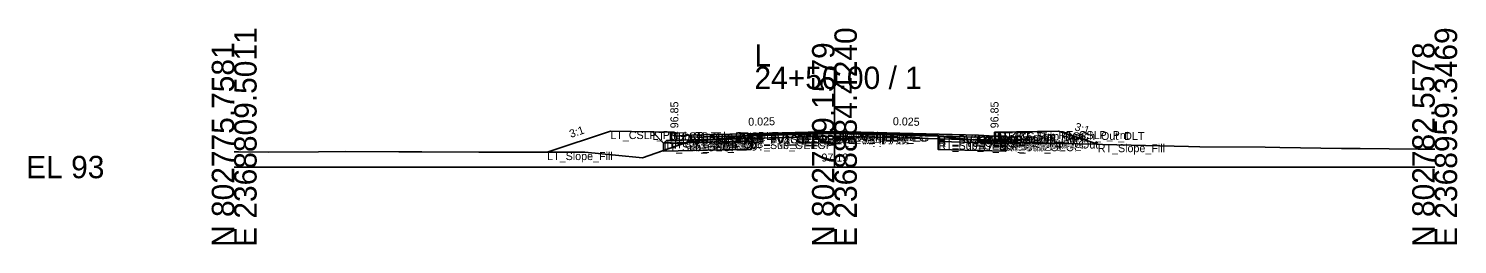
# Model space of a CAD drawing. Extents: x -26 to 8153, y -10 to 9520.
# Drawn here: x 974.3 to 1152.8, y 6990.3 to 7017.3 of the extents above; entities that cross this region are included whole.
import ezdxf

# ---------------------------------------------------------------- set-up
doc = ezdxf.new("R2010")
doc.units = 0
for name, color, linetype in [('Exist CMT Pavement', 7, 'Continuous'), ('Exist Cross Section Cell', 7, 'Continuous'), ('Exist XS Center Line Elevation Label', 7, 'Continuous'), ('Exist XS Ground Line', 7, 'Continuous'), ('Prop CMT Conc Surface', 7, 'Continuous'), ('Prop CMT Concrete Structures', 7, 'Continuous'), ('Prop CMT Pvmt Course 1', 7, 'Continuous'), ('Prop CMT Pvmt Course 1 CG', 7, 'Continuous'), ('Prop CMT Pvmt Course 1 Wedge', 7, 'Continuous'), ('Prop CMT Pvmt Course 2', 7, 'Continuous'), ('Prop CMT Pvmt Course 2 Wedge', 7, 'Continuous'), ('Prop CMT Pvmt Course 3', 7, 'Continuous'), ('Prop CMT Pvmt Course 3 Wedge', 7, 'Continuous'), ('Prop CMT Pvmt Surface', 7, 'Continuous'), ('Prop CMT Pvmt Wedge Surface 1', 7, 'Continuous'), ('Prop CMT Pvmt Wedge Surface 2', 7, 'Continuous'), ('Prop CMT Pvmt Wedge Surface 3', 7, 'Continuous'), ('Prop CMT Shallow Undercut', 7, 'Continuous'), ('Prop CMT Shallow Undercut Boundary', 7, 'Continuous'), ('Prop CMT Slope Grass', 7, 'Continuous'), ('Prop CMT Subgrade Earthwork', 7, 'Continuous'), ('Prop XS Earthwork Shape', 7, 'Continuous'), ('Prop XS Hydro Elevations', 7, 'Continuous'), ('Prop XS SE Text', 7, 'Continuous'), ('Prop XS Side Slope Text', 7, 'Continuous'), ('Prop XS Subgrade Earthwork', 7, 'Continuous'), ('Scratch_Level_2', 7, 'Continuous'), ('Scratch_Level_6', 7, 'Continuous')]:
    doc.layers.add(name, color=color, linetype=linetype)

msp = doc.modelspace()

# ---------------------------------------------------------------- linework, layer by layer
at = {"layer": 'Exist CMT Pavement'}
for p, q in [((1064.64, 7003.97), (1067.28, 7004.03)), ((1067.28, 7004.03), (1074.93, 7004.19)), ((1074.93, 7004.19), (1081.41, 7004.14)), ((1081.41, 7004.14), (1085.45, 7004.12)), ((1085.45, 7004.12), (1087.05, 7003.95)), ((1087.05, 7003.95), (1087.98, 7003.86))]:
    msp.add_line(p, q, dxfattribs=at)
at = {"layer": 'Exist Cross Section Cell'}
for p, q in [((1075, 7000), (1075, 7012.57)), ((1000, 7000), (1075, 7000)), ((1075, 7000), (1150, 7000))]:
    msp.add_line(p, q, dxfattribs=at)
at = {"layer": 'Exist XS Ground Line'}
for p, q in [((1062.93, 7003.77), (1064.64, 7003.97)), ((1064.64, 7003.97), (1067.28, 7004.03)), ((1067.28, 7004.03), (1074.93, 7004.19)), ((1074.93, 7004.19), (1081.41, 7004.14)), ((1081.41, 7004.14), (1085.45, 7004.12)), ((1085.45, 7004.12), (1087.05, 7003.95)), ((1087.05, 7003.95), (1087.98, 7003.86)), ((1087.98, 7003.86), (1089.65, 7003.66)), ((1051.03, 7001.16), (1056.73, 7003.17)), ((1056.73, 7003.17), (1060.65, 7003.54)), ((1060.65, 7003.54), (1062.93, 7003.77)), ((1089.65, 7003.66), (1093.02, 7003.36)), ((1093.02, 7003.36), (1098.57, 7003.08)), ((1098.57, 7003.08), (1100.93, 7002.99)), ((1100.93, 7002.99), (1107.75, 7002.88)), ((1107.75, 7002.88), (1108.48, 7002.82)), ((1108.48, 7002.82), (1119.22, 7002.57)), ((1119.22, 7002.57), (1120.65, 7002.53)), ((1120.65, 7002.53), (1128.8, 7002.48)), ((1128.8, 7002.48), (1130.66, 7002.45)), ((1130.66, 7002.45), (1138.37, 7002.32)), ((1138.37, 7002.32), (1140.67, 7002.32)), ((1140.67, 7002.32), (1147.95, 7002.24)), ((1147.95, 7002.24), (1150, 7002.22)), ((1000, 7001.9), (1000.52, 7001.9)), ((1000.52, 7001.9), (1004.31, 7001.88)), ((1004.31, 7001.88), (1010.53, 7001.9)), ((1010.53, 7001.9), (1013.88, 7001.93)), ((1013.88, 7001.93), (1020.55, 7001.92)), ((1020.55, 7001.92), (1023.46, 7001.92)), ((1023.46, 7001.92), (1030.56, 7001.86)), ((1030.56, 7001.86), (1032.55, 7001.86)), ((1032.55, 7001.86), (1043.8, 7001.87)), ((1043.8, 7001.87), (1047.64, 7001.49)), ((1047.64, 7001.49), (1051.03, 7001.16))]:
    msp.add_line(p, q, dxfattribs=at)
at = {"layer": 'Prop CMT Conc Surface'}
for points in [[(1055, 7003.85), (1055, 7004.35), (1054.5, 7004.35)], [(1057, 7003.98), (1055, 7003.85)], [(1093, 7003.98), (1095, 7003.85)], [(1095, 7003.85), (1095, 7004.35), (1095.5, 7004.35)]]:
    msp.add_lwpolyline(points, dxfattribs=at)
at = {"layer": 'Prop CMT Concrete Structures'}
for points in [[(1057, 7003.98), (1055, 7003.85), (1055, 7004.35), (1054.5, 7004.35)], [(1054.5, 7004.35), (1054.5, 7003.33), (1057, 7003.39)], [(1057, 7003.39), (1057, 7003.98)], [(1093, 7003.98), (1095, 7003.85), (1095, 7004.35), (1095.5, 7004.35)], [(1095.5, 7004.35), (1095.5, 7003.33), (1093, 7003.39)], [(1093, 7003.39), (1093, 7003.98)]]:
    msp.add_lwpolyline(points, dxfattribs=at)
at = {"layer": 'Prop CMT Pvmt Course 1'}
for points in [[(1075, 7004.43), (1057, 7003.98)], [(1057, 7003.98), (1057, 7003.73)], [(1057, 7003.73), (1064.64, 7003.92)], [(1064.64, 7004.04), (1075, 7004.3)], [(1064.64, 7003.92), (1064.64, 7004.04)], [(1075, 7004.18), (1075, 7004.43)], [(1075, 7004.43), (1093, 7003.98)], [(1075, 7004.18), (1075, 7004.43)], [(1075, 7004.3), (1075, 7004.18), (1075, 7004.18)], [(1087.98, 7003.98), (1075, 7004.3)], [(1075, 7004.3), (1075, 7004.18), (1075, 7004.18)], [(1087.98, 7003.85), (1087.98, 7003.98)], [(1093, 7003.73), (1087.98, 7003.85)], [(1093, 7003.98), (1093, 7003.73)]]:
    msp.add_lwpolyline(points, dxfattribs=at)
at = {"layer": 'Prop CMT Pvmt Course 1 CG'}
for points in [[(1057, 7003.39), (1054, 7003.32), (1053.66, 7002.98)], [(1053.66, 7002.98), (1057, 7003.06)], [(1057, 7003.06), (1057, 7003.39)], [(1093, 7003.39), (1096, 7003.32), (1096.34, 7002.98)], [(1093, 7003.06), (1093, 7003.39)], [(1096.34, 7002.98), (1093, 7003.06)]]:
    msp.add_lwpolyline(points, dxfattribs=at)
at = {"layer": 'Prop CMT Pvmt Course 1 Wedge'}
for points in [[(1075, 7004.3), (1064.64, 7004.04)], [(1075, 7004.3), (1087.98, 7003.98)]]:
    msp.add_lwpolyline(points, dxfattribs=at)
at = {"layer": 'Prop CMT Pvmt Course 2'}
for points in [[(1064.64, 7003.92), (1057, 7003.73)], [(1064.64, 7003.59), (1064.64, 7003.92)], [(1087.98, 7003.52), (1087.98, 7003.85)], [(1087.98, 7003.85), (1093, 7003.73)], [(1057, 7003.73), (1057, 7003.4)], [(1057, 7003.4), (1064.64, 7003.59)], [(1093, 7003.4), (1087.98, 7003.52)], [(1093, 7003.73), (1093, 7003.4)]]:
    msp.add_lwpolyline(points, dxfattribs=at)
at = {"layer": 'Prop CMT Pvmt Course 2 Wedge'}
for points in [[(1075, 7004.18), (1064.64, 7003.92)], [(1075, 7004.18), (1087.98, 7003.85)]]:
    msp.add_lwpolyline(points, dxfattribs=at)
at = {"layer": 'Prop CMT Pvmt Course 3'}
for points in [[(1064.64, 7003.59), (1057, 7003.4)], [(1057, 7003.4), (1057, 7003.06)], [(1057, 7003.06), (1064.64, 7003.25)], [(1064.64, 7003.25), (1064.64, 7003.59)], [(1087.98, 7003.52), (1093, 7003.4)], [(1087.98, 7003.19), (1087.98, 7003.52)], [(1093, 7003.06), (1087.98, 7003.19)], [(1093, 7003.4), (1093, 7003.06)]]:
    msp.add_lwpolyline(points, dxfattribs=at)
at = {"layer": 'Prop CMT Pvmt Course 3 Wedge'}
for points in [[(1075, 7003.85), (1064.64, 7003.59)], [(1075, 7003.85), (1087.98, 7003.52)]]:
    msp.add_lwpolyline(points, dxfattribs=at)
at = {"layer": 'Prop CMT Pvmt Surface'}
for points in [[(1075, 7004.43), (1057, 7003.98)], [(1075, 7004.43), (1093, 7003.98)]]:
    msp.add_lwpolyline(points, dxfattribs=at)
at = {"layer": 'Prop CMT Pvmt Wedge Surface 1'}
for points in [[(1057, 7003.73), (1057, 7003.98)], [(1064.64, 7003.92), (1057, 7003.73)], [(1075, 7004.3), (1064.64, 7004.04)], [(1064.64, 7004.04), (1064.64, 7003.92)], [(1075, 7004.3), (1087.98, 7003.98)], [(1087.98, 7003.98), (1087.98, 7003.85)], [(1087.98, 7003.85), (1093, 7003.73)], [(1093, 7003.73), (1093, 7003.98)]]:
    msp.add_lwpolyline(points, dxfattribs=at)
at = {"layer": 'Prop CMT Pvmt Wedge Surface 2'}
for points in [[(1075, 7004.18), (1057, 7003.73)], [(1057, 7003.73), (1057, 7003.98)], [(1075, 7004.18), (1093, 7003.73)], [(1093, 7003.73), (1093, 7003.98)]]:
    msp.add_lwpolyline(points, dxfattribs=at)
at = {"layer": 'Prop CMT Pvmt Wedge Surface 3'}
for points in [[(1057, 7003.4), (1057, 7003.98)], [(1075, 7003.85), (1057, 7003.4)], [(1075, 7003.85), (1093, 7003.4)], [(1093, 7003.4), (1093, 7003.98)]]:
    msp.add_lwpolyline(points, dxfattribs=at)
at = {"layer": 'Prop CMT Shallow Undercut'}
for p, q in [((1096.34, 7002.98), (1087.98, 7003.19)), ((1087.98, 7003.19), (1087.98, 7002.19)), ((1087.98, 7002.19), (1096.34, 7001.98)), ((1096.34, 7001.98), (1096.34, 7002.98))]:
    msp.add_line(p, q, dxfattribs=at)
msp.add_lwpolyline([(1064.64, 7003.25), (1064.64, 7002.25), (1053.66, 7001.98), (1053.66, 7002.09), (1056.4, 7003.05)], close=True, dxfattribs=at)
at = {"layer": 'Prop CMT Shallow Undercut Boundary'}
for p, q in [((1053.66, 7002.98), (1064.64, 7003.25)), ((1053.66, 7002.98), (1053.66, 7001.98)), ((1053.66, 7001.98), (1064.64, 7002.25)), ((1064.64, 7003.25), (1064.64, 7002.25)), ((1087.98, 7003.19), (1087.98, 7002.19)), ((1087.98, 7003.19), (1096.34, 7002.98)), ((1087.98, 7002.19), (1096.34, 7001.98)), ((1096.34, 7002.98), (1096.34, 7001.98))]:
    msp.add_line(p, q, dxfattribs=at)
at = {"layer": 'Prop CMT Slope Grass'}
for points in [[(1054.5, 7004.35), (1047, 7004.5), (1039.11, 7001.87)], [(1095.5, 7004.35), (1103, 7004.5), (1107.9, 7002.86)]]:
    msp.add_lwpolyline(points, dxfattribs=at)
at = {"layer": 'Prop CMT Subgrade Earthwork'}
for points in [[(1057, 7003.06), (1053.66, 7002.98), (1052.25, 7004.39)], [(1064.64, 7003.25), (1064.66, 7003.97)], [(1087.98, 7003.19), (1087.97, 7003.86)], [(1093, 7003.06), (1096.34, 7002.98), (1097.75, 7004.39)], [(1064.64, 7003.25), (1057, 7003.06)], [(1087.98, 7003.19), (1093, 7003.06)]]:
    msp.add_lwpolyline(points, dxfattribs=at)
at = {"layer": 'Prop XS Earthwork Shape'}
for points in [[(1047, 7004.5), (1039.11, 7001.87), (1043.8, 7001.87), (1047.64, 7001.49), (1051.03, 7001.16), (1053.66, 7002.09), (1053.66, 7002.98), (1052.25, 7004.39)], [(1057, 7003.06), (1056.4, 7003.05), (1056.73, 7003.17), (1060.65, 7003.54), (1062.93, 7003.77), (1064.64, 7003.97), (1064.66, 7003.97), (1064.64, 7003.25)], [(1087.97, 7003.86), (1087.98, 7003.86), (1089.65, 7003.66), (1093.02, 7003.36), (1096.54, 7003.19), (1096.34, 7002.98), (1093, 7003.06), (1087.98, 7003.19)], [(1098.57, 7003.08), (1100.93, 7002.99), (1107.75, 7002.88), (1107.9, 7002.86), (1103, 7004.5), (1097.75, 7004.39), (1096.54, 7003.19)], [(1057, 7003.06), (1056.4, 7003.05), (1053.66, 7002.09), (1053.66, 7001.98), (1064.64, 7002.25), (1064.64, 7003.25)], [(1056.4, 7003.05), (1053.66, 7002.98), (1053.66, 7002.09)], [(1096.34, 7002.98), (1096.34, 7001.98), (1087.98, 7002.19), (1087.98, 7003.19), (1093, 7003.06)]]:
    msp.add_lwpolyline(points, close=True, dxfattribs=at)
at = {"layer": 'Prop XS Subgrade Earthwork'}
for p, q in [((1053.66, 7002.98), (1064.64, 7003.25)), ((1096.34, 7002.98), (1087.98, 7003.19))]:
    msp.add_line(p, q, dxfattribs=at)
at = {"layer": 'Scratch_Level_6'}
for p, q in [((1096.34, 7002.98), (1087.98, 7003.19)), ((1087.98, 7003.19), (1087.98, 7002.19)), ((1087.98, 7002.19), (1096.34, 7001.98)), ((1096.34, 7001.98), (1096.34, 7002.98))]:
    msp.add_line(p, q, dxfattribs=at)
msp.add_lwpolyline([(1064.64, 7003.25), (1064.64, 7002.25), (1053.66, 7001.98), (1053.66, 7002.09), (1056.4, 7003.05)], close=True, dxfattribs=at)

# ---------------------------------------------------------------- texts
at = {"layer": 'Exist Cross Section Cell'}
for s, p in [('E 2368809.5011', (1002.8, 6990)), ('E 2368884.4240', (1077.8, 6990)), ('E 2368959.3469', (1152.8, 6990)), ('N 802775.7581', (1000, 6990)), ('N 802779.1579', (1075, 6990)), ('N 802782.5578', (1150, 6990))]:
    msp.add_text(s, height=2.8, rotation=90, dxfattribs=at).set_placement(p)
for s, p in [('L', (1065, 7012.57)), ('24+50.00 / 1', (1065, 7009.77)), ('EL 93', (974, 6998.6))]:
    msp.add_text(s, height=2.8, dxfattribs=at).set_placement(p)
at = {"layer": 'Exist XS Center Line Elevation Label'}
msp.add_text('97.19', height=1, dxfattribs=at).set_placement((1073.38, 7000.69))
at = {"layer": 'Prop XS Hydro Elevations'}
for p in [(1055.5, 7004.85), (1095.5, 7004.85)]:
    msp.add_text('96.85', height=1, rotation=90, dxfattribs=at).set_placement(p)
at = {"layer": 'Prop XS SE Text'}
for rotation, p in [(1.4321, (1064.24, 7005.16)), (358.5679, (1082.29, 7005.24))]:
    msp.add_text('0.025', height=1, rotation=rotation, dxfattribs=at).set_placement(p)
at = {"layer": 'Prop XS Side Slope Text'}
for rotation, p in [(18.4349, (1042.07, 7003.64)), (341.5651, (1104.93, 7004.64))]:
    msp.add_text('3:1', height=1, rotation=rotation, dxfattribs=at).set_placement(p)
at = {"layer": 'Scratch_Level_2'}
for s, p in [('LT_CSLP_Pnt', (1047, 7003.5)), ('LT_Sub_Trench_Out_DLT', (1052.25, 7003.39)), ('LT_CG_Top_BOC', (1054.5, 7003.35)), ('LT_CG_Top_Face', (1055, 7003.35)), ('LT_CG_Top_Gut', (1055, 7002.85)), ('LT_PV1_OEOT', (1057, 7002.98)), ('LT_PV1_OEEOP', (1064.64, 7003.04)), ('LT_PV_OEEOP_EG', (1064.64, 7002.97)), ('LT_PV2_OEEOP', (1064.64, 7002.92)), ('LT_PV_Sub_Tie_Out', (1064.66, 7002.97)), ('PV1_PGL', (1075, 7003.43)), ('RT_PV1_IEEOP', (1075, 7003.3)), ('LT_PV1_IEEOP', (1075, 7003.3)), ('RT_PV_IEEOP_EG', (1075, 7003.19)), ('LT_PV_IEEOP_EG', (1075, 7003.19)), ('RT_PV2_IEEOP', (1075, 7003.18)), ('LT_PV2_IEEOP', (1075, 7003.18)), ('PV2_PGL', (1075, 7003.18)), ('RT_PV3_IEEOP', (1075, 7002.85)), ('LT_PV3_IEEOP', (1075, 7002.85)), ('RT_PV_Sub_Tie_Out', (1087.97, 7002.86)), ('RT_PV1_OEEOP', (1087.98, 7002.98)), ('RT_PV_OEEOP_EG', (1087.98, 7002.86)), ('RT_PV2_OEEOP', (1087.98, 7002.85)), ('RT_PV1_OEOT', (1093, 7002.98)), ('RT_CG_Top_Face', (1095, 7003.35)), ('RT_CG_Top_Gut', (1095, 7002.85)), ('RT_CG_Top_BOC', (1095.5, 7003.35)), ('RT_Sub_Trench_Out_DLT', (1097.75, 7003.39)), ('RT_CSLP_Pnt', (1103, 7003.5)), ('LT_Sub_OEOP', (1053.66, 7001.98)), ('LT_CG1_Shelf_Out', (1054, 7002.32)), ('LT_CG_Bot_BOC', (1054.5, 7002.33)), ('LT_PV2_OEOT', (1057, 7002.73)), ('LT_PV3_OEOT', (1057, 7002.4)), ('LT_CG_Bot_IE', (1057, 7002.39)), ('LT_Sub_OEOT', (1057, 7002.06)), ('LT_PV3_OEEOP', (1064.64, 7002.59)), ('LT_Sub_OEEOP', (1064.64, 7002.25)), ('RT_PV3_OEEOP', (1087.98, 7002.52)), ('RT_Sub_OEEOP', (1087.98, 7002.19)), ('RT_PV2_OEOT', (1093, 7002.73)), ('RT_PV3_OEOT', (1093, 7002.4)), ('RT_CG_Bot_IE', (1093, 7002.39)), ('RT_Sub_OEOT', (1093, 7002.06)), ('RT_CG_Bot_BOC', (1095.5, 7002.33)), ('RT_CG1_Shelf_Out', (1096, 7002.32)), ('RT_Sub_OEOP', (1096.34, 7001.98)), ('RT_Slope_Fill', (1107.9, 7001.86)), ('LT_Slope_Fill', (1039.11, 7000.87))]:
    msp.add_text(s, height=1, dxfattribs=at).set_placement(p)

doc.saveas('drawing.dxf')
